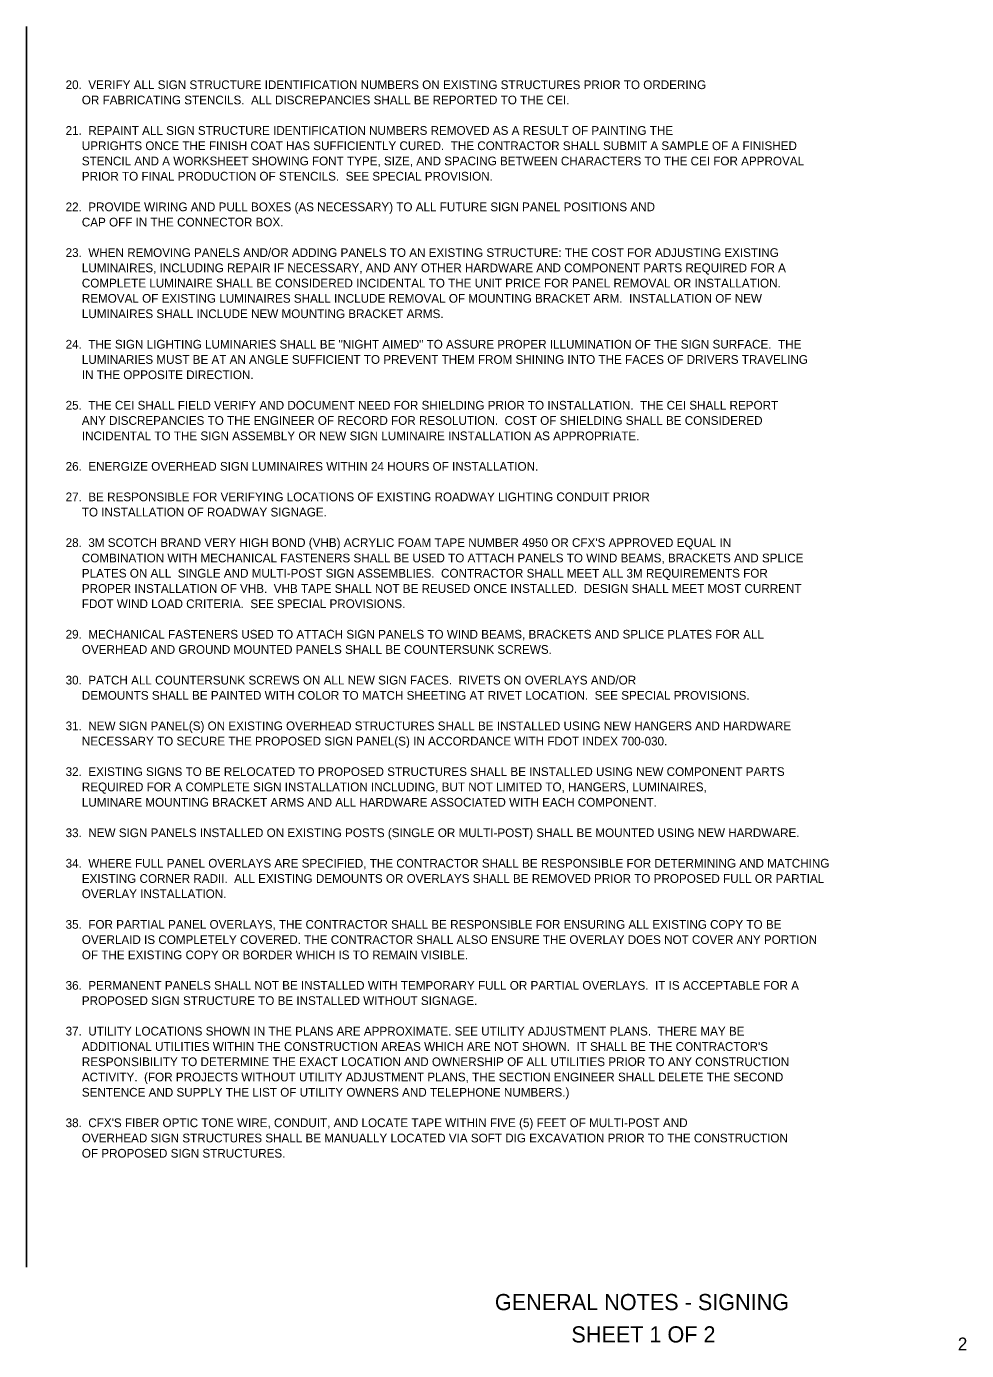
# Model space of a CAD drawing. Extents: x 2479946 to 2481498, y 3680184 to 3681234.
# Drawn here: x 2480771 to 2481498, y 3680210 to 3681234 of the extents above; entities that cross this region are included whole.
import ezdxf

# ---------------------------------------------------------------- set-up
doc = ezdxf.new("R2010")
doc.units = 0
for name, color, linetype in [('NonPlottingEle_dp', 7, 'Continuous'), ('TextLabel', 7, 'Continuous'), ('TextMisc', 7, 'Continuous'), ('TextShtNo', 7, 'Continuous')]:
    doc.layers.add(name, color=color, linetype=linetype)

msp = doc.modelspace()

# ---------------------------------------------------------------- linework, layer by layer
at = {"layer": 'NonPlottingEle_dp'}
msp.add_line((2480770.9, 3680274.2), (2480770.9, 3681234.2), dxfattribs=at)

# ---------------------------------------------------------------- texts
at = {"layer": 'TextLabel'}
for s, p in [('20.  VERIFY ALL SIGN STRUCTURE IDENTIFICATION NUMBERS ON EXISTING STRUCTURES PRIOR TO ORDERING', (2480801.2, 3681185.8)), ('     OR FABRICATING STENCILS.  ALL DISCREPANCIES SHALL BE REPORTED TO THE CEI.', (2480801.2, 3681174)), ('21.  REPAINT ALL SIGN STRUCTURE IDENTIFICATION NUMBERS REMOVED AS A RESULT OF PAINTING THE', (2480801.2, 3681150.4)), ('     UPRIGHTS ONCE THE FINISH COAT HAS SUFFICIENTLY CURED.  THE CONTRACTOR SHALL SUBMIT A SAMPLE OF A FINISHED', (2480801.2, 3681138.6)), ('     STENCIL AND A WORKSHEET SHOWING FONT TYPE, SIZE, AND SPACING BETWEEN CHARACTERS TO THE CEI FOR APPROVAL', (2480801.2, 3681126.8)), ('     PRIOR TO FINAL PRODUCTION OF STENCILS.  SEE SPECIAL PROVISION.', (2480801.2, 3681115)), ('22.  PROVIDE WIRING AND PULL BOXES (AS NECESSARY) TO ALL FUTURE SIGN PANEL POSITIONS AND ', (2480801.2, 3681091.3)), ('     CAP OFF IN THE CONNECTOR BOX.', (2480801.2, 3681079.5)), ('23.  WHEN REMOVING PANELS AND/OR ADDING PANELS TO AN EXISTING STRUCTURE: THE COST FOR ADJUSTING EXISTING', (2480801.2, 3681055.9)), ('     LUMINAIRES, INCLUDING REPAIR IF NECESSARY, AND ANY OTHER HARDWARE AND COMPONENT PARTS REQUIRED FOR A', (2480801.2, 3681044.1)), ('     COMPLETE LUMINAIRE SHALL BE CONSIDERED INCIDENTAL TO THE UNIT PRICE FOR PANEL REMOVAL OR INSTALLATION.', (2480801.2, 3681032.3)), ('     REMOVAL OF EXISTING LUMINAIRES SHALL INCLUDE REMOVAL OF MOUNTING BRACKET ARM.  INSTALLATION OF NEW', (2480801.2, 3681020.5)), ('     LUMINAIRES SHALL INCLUDE NEW MOUNTING BRACKET ARMS.', (2480801.2, 3681008.6)), ('24.  THE SIGN LIGHTING LUMINARIES SHALL BE "NIGHT AIMED" TO ASSURE PROPER ILLUMINATION OF THE SIGN SURFACE.  THE ', (2480801.2, 3680985)), ('     LUMINARIES MUST BE AT AN ANGLE SUFFICIENT TO PREVENT THEM FROM SHINING INTO THE FACES OF DRIVERS TRAVELING ', (2480801.2, 3680973.2)), ('     IN THE OPPOSITE DIRECTION.', (2480801.2, 3680961.4)), ('25.  THE CEI SHALL FIELD VERIFY AND DOCUMENT NEED FOR SHIELDING PRIOR TO INSTALLATION.  THE CEI SHALL REPORT', (2480801.2, 3680937.8)), ('     ANY DISCREPANCIES TO THE ENGINEER OF RECORD FOR RESOLUTION.  COST OF SHIELDING SHALL BE CONSIDERED', (2480801.2, 3680926)), ('     INCIDENTAL TO THE SIGN ASSEMBLY OR NEW SIGN LUMINAIRE INSTALLATION AS APPROPRIATE.', (2480801.2, 3680914.1)), ('26.  ENERGIZE OVERHEAD SIGN LUMINAIRES WITHIN 24 HOURS OF INSTALLATION.', (2480801.2, 3680890.5)), ('27.  BE RESPONSIBLE FOR VERIFYING LOCATIONS OF EXISTING ROADWAY LIGHTING CONDUIT PRIOR ', (2480801.2, 3680866.9)), ('     TO INSTALLATION OF ROADWAY SIGNAGE.', (2480801.2, 3680855.1)), ("28.  3M SCOTCH BRAND VERY HIGH BOND (VHB) ACRYLIC FOAM TAPE NUMBER 4950 OR CFX'S APPROVED EQUAL IN ", (2480801.2, 3680831.5)), ('     COMBINATION WITH MECHANICAL FASTENERS SHALL BE USED TO ATTACH PANELS TO WIND BEAMS, BRACKETS AND SPLICE ', (2480801.2, 3680819.6)), ('     PLATES ON ALL  SINGLE AND MULTI-POST SIGN ASSEMBLIES.  CONTRACTOR SHALL MEET ALL 3M REQUIREMENTS FOR', (2480801.2, 3680807.8)), ('     PROPER INSTALLATION OF VHB.  VHB TAPE SHALL NOT BE REUSED ONCE INSTALLED.  DESIGN SHALL MEET MOST CURRENT ', (2480801.2, 3680796)), ('     FDOT WIND LOAD CRITERIA.  SEE SPECIAL PROVISIONS.', (2480801.2, 3680784.2)), ('29.  MECHANICAL FASTENERS USED TO ATTACH SIGN PANELS TO WIND BEAMS, BRACKETS AND SPLICE PLATES FOR ALL ', (2480801.2, 3680760.6)), ('     OVERHEAD AND GROUND MOUNTED PANELS SHALL BE COUNTERSUNK SCREWS.', (2480801.2, 3680748.8)), ('30.  PATCH ALL COUNTERSUNK SCREWS ON ALL NEW SIGN FACES.  RIVETS ON OVERLAYS AND/OR ', (2480801.2, 3680725.1)), ('     DEMOUNTS SHALL BE PAINTED WITH COLOR TO MATCH SHEETING AT RIVET LOCATION.  SEE SPECIAL PROVISIONS.', (2480801.2, 3680713.3)), ('31.  NEW SIGN PANEL(S) ON EXISTING OVERHEAD STRUCTURES SHALL BE INSTALLED USING NEW HANGERS AND HARDWARE', (2480801.2, 3680689.7)), ('     NECESSARY TO SECURE THE PROPOSED SIGN PANEL(S) IN ACCORDANCE WITH FDOT INDEX 700-030.  ', (2480801.2, 3680677.9)), ('32.  EXISTING SIGNS TO BE RELOCATED TO PROPOSED STRUCTURES SHALL BE INSTALLED USING NEW COMPONENT PARTS ', (2480801.2, 3680654.3)), ('     REQUIRED FOR A COMPLETE SIGN INSTALLATION INCLUDING, BUT NOT LIMITED TO, HANGERS, LUMINAIRES, ', (2480801.2, 3680642.5)), ('     LUMINARE MOUNTING BRACKET ARMS AND ALL HARDWARE ASSOCIATED WITH EACH COMPONENT.', (2480801.2, 3680630.6)), ('33.  NEW SIGN PANELS INSTALLED ON EXISTING POSTS (SINGLE OR MULTI-POST) SHALL BE MOUNTED USING NEW HARDWARE.', (2480801.2, 3680607)), ('34.  WHERE FULL PANEL OVERLAYS ARE SPECIFIED, THE CONTRACTOR SHALL BE RESPONSIBLE FOR DETERMINING AND MATCHING', (2480801.2, 3680583.4)), ('     EXISTING CORNER RADII.  ALL EXISTING DEMOUNTS OR OVERLAYS SHALL BE REMOVED PRIOR TO PROPOSED FULL OR PARTIAL', (2480801.2, 3680571.6)), ('     OVERLAY INSTALLATION.', (2480801.2, 3680559.8)), ('35.  FOR PARTIAL PANEL OVERLAYS, THE CONTRACTOR SHALL BE RESPONSIBLE FOR ENSURING ALL EXISTING COPY TO BE', (2480801.2, 3680536.1)), ('     OVERLAID IS COMPLETELY COVERED. THE CONTRACTOR SHALL ALSO ENSURE THE OVERLAY DOES NOT COVER ANY PORTION', (2480801.2, 3680524.3)), ('     OF THE EXISTING COPY OR BORDER WHICH IS TO REMAIN VISIBLE.', (2480801.2, 3680512.5)), ('36.  PERMANENT PANELS SHALL NOT BE INSTALLED WITH TEMPORARY FULL OR PARTIAL OVERLAYS.  IT IS ACCEPTABLE FOR A', (2480801.2, 3680488.9)), ('     PROPOSED SIGN STRUCTURE TO BE INSTALLED WITHOUT SIGNAGE.', (2480801.2, 3680477.1)), ('37.  UTILITY LOCATIONS SHOWN IN THE PLANS ARE APPROXIMATE. SEE UTILITY ADJUSTMENT PLANS.  THERE MAY BE ', (2480801.2, 3680453.5)), ("     ADDITIONAL UTILITIES WITHIN THE CONSTRUCTION AREAS WHICH ARE NOT SHOWN.  IT SHALL BE THE CONTRACTOR'S ", (2480801.2, 3680441.6)), ('     RESPONSIBILITY TO DETERMINE THE EXACT LOCATION AND OWNERSHIP OF ALL UTILITIES PRIOR TO ANY CONSTRUCTION ', (2480801.2, 3680429.8)), ('     ACTIVITY.  (FOR PROJECTS WITHOUT UTILITY ADJUSTMENT PLANS, THE SECTION ENGINEER SHALL DELETE THE SECOND', (2480801.2, 3680418)), ('     SENTENCE AND SUPPLY THE LIST OF UTILITY OWNERS AND TELEPHONE NUMBERS.)', (2480801.2, 3680406.2)), ("38.  CFX'S FIBER OPTIC TONE WIRE, CONDUIT, AND LOCATE TAPE WITHIN FIVE (5) FEET OF MULTI-POST AND ", (2480801.2, 3680382.6)), ('     OVERHEAD SIGN STRUCTURES SHALL BE MANUALLY LOCATED VIA SOFT DIG EXCAVATION PRIOR TO THE CONSTRUCTION ', (2480801.2, 3680370.8)), ('     OF PROPOSED SIGN STRUCTURES.', (2480801.2, 3680359))]:
    msp.add_text(s, height=6.75, dxfattribs=at).set_placement(p)
at = {"layer": 'TextMisc'}
for s, p in [('GENERAL NOTES - SIGNING ', (2481133.3, 3680241)), ('      SHEET 1 OF 2      ', (2481164.6, 3680216))]:
    msp.add_text(s, height=12.5, rotation=360, dxfattribs=at).set_placement(p)
at = {"layer": 'TextShtNo'}
msp.add_text('  2   ', height=10, rotation=360, dxfattribs=at).set_placement((2481483.9, 3680209.8))

doc.saveas('drawing.dxf')
